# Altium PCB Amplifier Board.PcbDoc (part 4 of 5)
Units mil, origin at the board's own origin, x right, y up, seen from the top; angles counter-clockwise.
Board outline 6000 x 4000 mil, 6 copper layers (Top Layer, GND, VCC, InternalPlane3, InternalPlane4, Bottom Layer); 880 components, 519 nets, 2020 pads, 372 vias.
Unrouted connection lines stored in the file: 585.
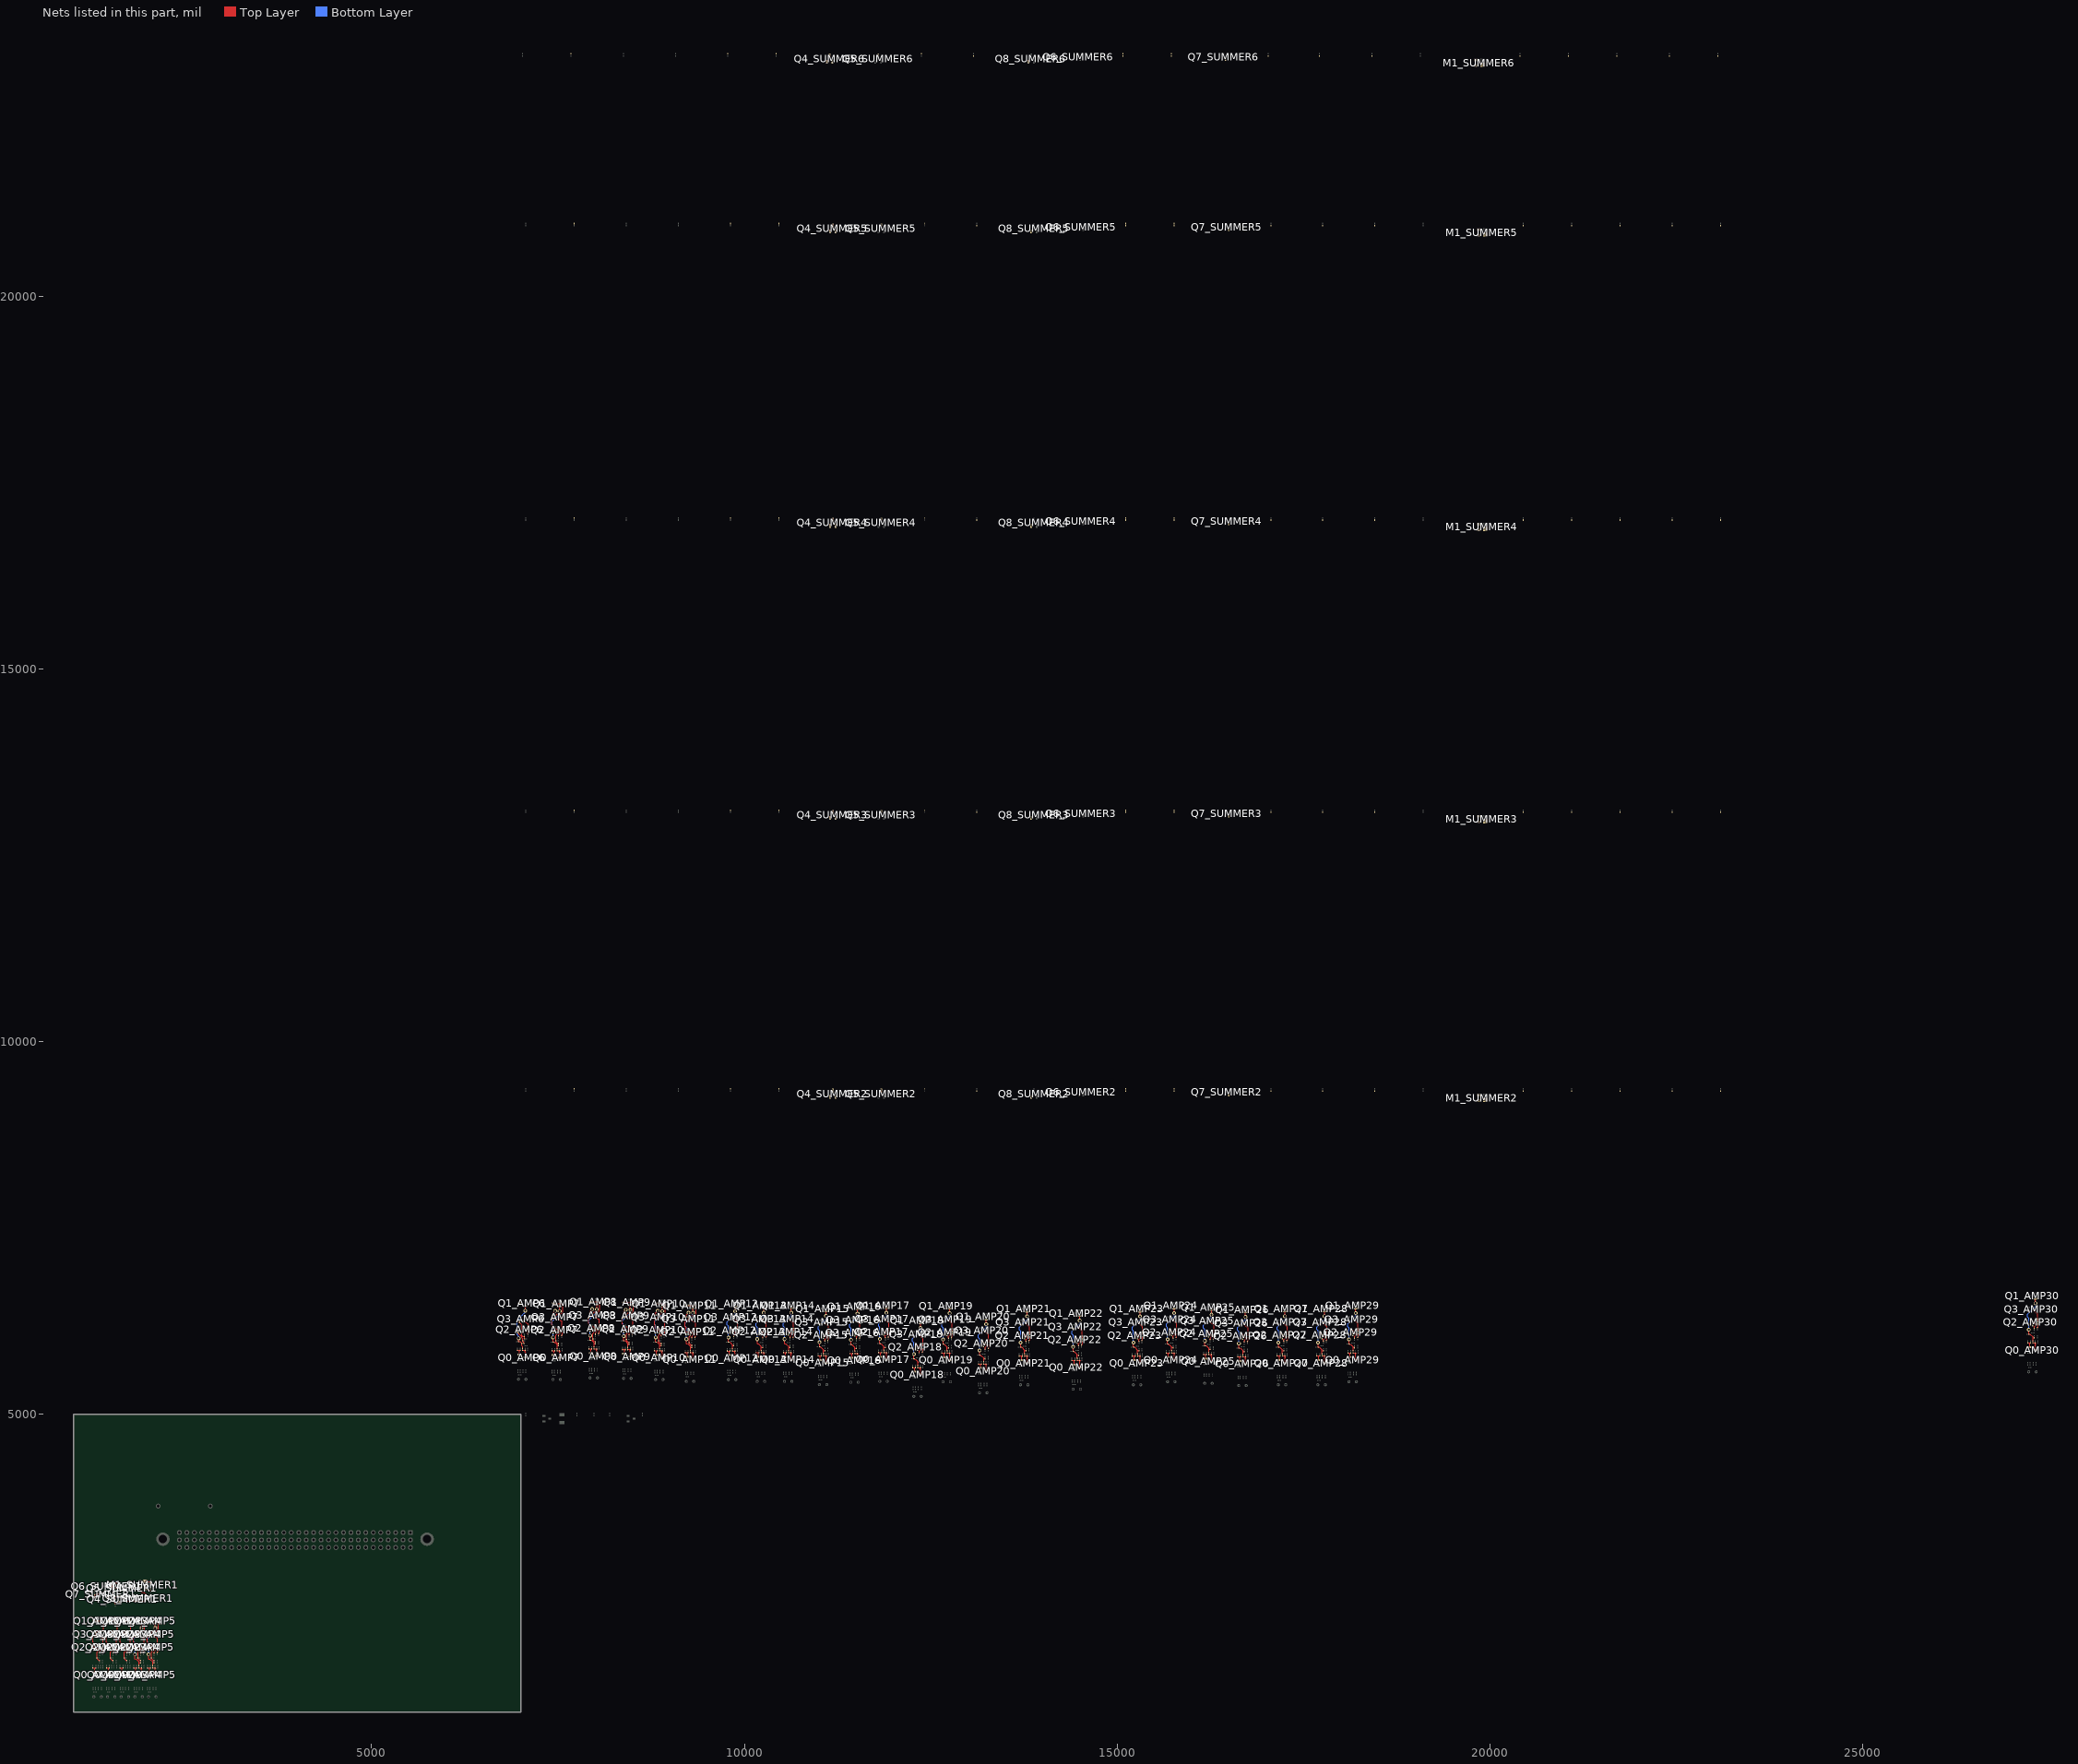
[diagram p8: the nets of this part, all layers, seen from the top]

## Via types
v1: diameter 50, hole 28, Top Layer to Bottom Layer, 371 vias
v2: diameter 50, hole 28, Top Layer to Bottom Layer, tented top, 1 vias

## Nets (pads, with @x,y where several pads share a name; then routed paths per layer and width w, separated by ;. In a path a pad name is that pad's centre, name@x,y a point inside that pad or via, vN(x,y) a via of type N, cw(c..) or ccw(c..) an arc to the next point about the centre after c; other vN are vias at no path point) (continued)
NetC4_AMP4_1: C4_AMP4.1 Q0_AMP4.3 R6_AMP4.1 | length 137.1
  Top Layer w7: C4_AMP4.1@1880,1596.22 R6_AMP4.1@1913,1596.22 ; Q0_AMP4.3@1915.34,1501.56 1915.34,1568.66 1913,1571 R6_AMP4.1@1913,1596.22 ; 1919,1590.22 R6_AMP4.1@1913,1596.22
NetC4_AMP4_2: C4_AMP4.2 Q1_AMP4.1 R2_AMP4.1 R3_AMP4.2 | length 660.4
  Top Layer w7: R3_AMP4.2@1826,1715.78 v1(1826,1776) ; R3_AMP4.2@1827.78,1714 1839,1714 ; 1842,1714 1880,1676 C4_AMP4.2@1880,1623.78 ; 1880,1666 R2_AMP4.1@1898.22,1666 ; v1@1915.34,2130.34 Q1_AMP4.1@1915.34,2191.6
  Bottom Layer w7: v1(1826,1776) 1826,1931 1809,1948 1809,1984 1914,2089 v1(1914,2129)
NetC4_AMP5_1: C4_AMP5.1 Q0_AMP5.3 R6_AMP5.1 | length 137.1
  Top Layer w7: C4_AMP5.1@2063,1596.22 R6_AMP5.1@2096,1596.22 ; Q0_AMP5.3@2098.34,1501.56 2098.34,1568.66 2096,1571 R6_AMP5.1@2096,1596.22 ; 2102,1590.22 R6_AMP5.1@2096,1596.22
NetC4_AMP5_2: C4_AMP5.2 Q1_AMP5.1 R2_AMP5.1 R3_AMP5.2 | length 660.4
  Top Layer w7: R3_AMP5.2@2009,1715.78 v1(2009,1776) ; R3_AMP5.2@2010.78,1714 2022,1714 ; 2025,1714 2063,1676 C4_AMP5.2@2063,1623.78 ; 2063,1666 R2_AMP5.1@2081.22,1666 ; v1@2098.34,2130.34 Q1_AMP5.1@2098.34,2191.6
  Bottom Layer w7: v1(2009,1776) 2009,1931 1992,1948 1992,1984 2097,2089 v1(2097,2129)
NetC4_AMP6_1: C4_AMP6.1 Q0_AMP6.3 R6_AMP6.1 | length 137.1
  Top Layer w7: C4_AMP6.1@7026,5856.22 R6_AMP6.1@7059,5856.22 ; Q0_AMP6.3@7061.34,5761.56 7061.34,5828.66 7059,5831 R6_AMP6.1@7059,5856.22 ; 7065,5850.22 R6_AMP6.1@7059,5856.22
NetC4_AMP6_2: C4_AMP6.2 Q1_AMP6.1 R2_AMP6.1 R3_AMP6.2 | length 653.2
  Top Layer w7: R3_AMP6.2@6972.4,5974 v1@6972.4,6018.6 ; R3_AMP6.2@6973.78,5974 6992.22,5974 R2_AMP6.1@7016.22,5950 7016.22,5922.78 7026,5913 C4_AMP6.2@7026,5883.78 ; v1@7061.34,6390.34 Q1_AMP6.1@7061.34,6451.6
  Bottom Layer w7: v1(6972,6019) 6972,6046 6950,6068 6950,6256 7060,6366 v1(7060,6389)
NetC4_AMP7_1: C4_AMP7.1 Q0_AMP7.3 R6_AMP7.1 | length 137.1
  Top Layer w7: C4_AMP7.1@7488,5851.22 R6_AMP7.1@7521,5851.22 ; Q0_AMP7.3@7523.34,5756.56 7523.34,5823.66 7521,5826 R6_AMP7.1@7521,5851.22 ; 7527,5845.22 R6_AMP7.1@7521,5851.22
NetC4_AMP7_2: C4_AMP7.2 Q1_AMP7.1 R2_AMP7.1 R3_AMP7.2 | length 660.4
  Top Layer w7: R3_AMP7.2@7434,5970.78 v1(7434,6031) ; R3_AMP7.2@7435.78,5969 7447,5969 ; 7450,5969 7488,5931 C4_AMP7.2@7488,5878.78 ; 7488,5921 R2_AMP7.1@7506.22,5921 ; v1@7523.34,6385.34 Q1_AMP7.1@7523.34,6446.6
  Bottom Layer w7: v1(7434,6031) 7434,6186 7417,6203 7417,6239 7522,6344 v1(7522,6384)
NetC4_AMP8_1: C4_AMP8.1 Q0_AMP8.3 R6_AMP8.1 | length 137.1
  Top Layer w7: C4_AMP8.1@7985,5875.22 R6_AMP8.1@8018,5875.22 ; Q0_AMP8.3@8020.34,5780.56 8020.34,5847.66 8018,5850 R6_AMP8.1@8018,5875.22 ; 8024,5869.22 R6_AMP8.1@8018,5875.22
NetC4_AMP8_2: C4_AMP8.2 Q1_AMP8.1 R2_AMP8.1 R3_AMP8.2 | length 660.4
  Top Layer w7: R3_AMP8.2@7931,5994.78 v1(7931,6055) ; R3_AMP8.2@7932.78,5993 7944,5993 ; 7947,5993 7985,5955 C4_AMP8.2@7985,5902.78 ; 7985,5945 R2_AMP8.1@8003.22,5945 ; v1@8020.34,6409.34 Q1_AMP8.1@8020.34,6470.6
  Bottom Layer w7: v1(7931,6055) 7931,6210 7914,6227 7914,6263 8019,6368 v1(8019,6408)
NetC4_AMP9_1: C4_AMP9.1 Q0_AMP9.3 R6_AMP9.1 | length 137.1
  Top Layer w7: C4_AMP9.1@8436,5868.22 R6_AMP9.1@8469,5868.22 ; Q0_AMP9.3@8471.34,5773.56 8471.34,5840.66 8469,5843 R6_AMP9.1@8469,5868.22 ; 8475,5862.22 R6_AMP9.1@8469,5868.22
NetC4_AMP9_2: C4_AMP9.2 Q1_AMP9.1 R2_AMP9.1 R3_AMP9.2 | length 660.4
  Top Layer w7: R3_AMP9.2@8382,5987.78 v1(8382,6048) ; R3_AMP9.2@8383.78,5986 8395,5986 ; 8398,5986 8436,5948 C4_AMP9.2@8436,5895.78 ; 8436,5938 R2_AMP9.1@8454.22,5938 ; v1@8471.34,6402.34 Q1_AMP9.1@8471.34,6463.6
  Bottom Layer w7: v1(8382,6048) 8382,6203 8365,6220 8365,6256 8470,6361 v1(8470,6401)
NetC4_AMP10_1: C4_AMP10.1 Q0_AMP10.3 R6_AMP10.1 | length 137.1
  Top Layer w7: C4_AMP10.1@8865,5851.22 R6_AMP10.1@8898,5851.22 ; Q0_AMP10.3@8900.34,5756.56 8900.34,5823.66 8898,5826 R6_AMP10.1@8898,5851.22 ; 8904,5845.22 R6_AMP10.1@8898,5851.22
NetC4_AMP10_2: C4_AMP10.2 Q1_AMP10.1 R2_AMP10.1 R3_AMP10.2 | length 660.4
  Top Layer w7: R3_AMP10.2@8811,5970.78 v1(8811,6031) ; R3_AMP10.2@8812.78,5969 8824,5969 ; 8827,5969 8865,5931 C4_AMP10.2@8865,5878.78 ; 8865,5921 R2_AMP10.1@8883.22,5921 ; v1@8900.34,6385.34 Q1_AMP10.1@8900.34,6446.6
  Bottom Layer w7: v1(8811,6031) 8811,6186 8794,6203 8794,6239 8899,6344 v1(8899,6384)
NetC4_AMP11_1: C4_AMP11.1 Q0_AMP11.3 R6_AMP11.1 | length 137.1
  Top Layer w7: C4_AMP11.1@9277,5827.22 R6_AMP11.1@9310,5827.22 ; Q0_AMP11.3@9312.34,5732.56 9312.34,5799.66 9310,5802 R6_AMP11.1@9310,5827.22 ; 9316,5821.22 R6_AMP11.1@9310,5827.22
NetC4_AMP11_2: C4_AMP11.2 Q1_AMP11.1 R2_AMP11.1 R3_AMP11.2 | length 660.4
  Top Layer w7: R3_AMP11.2@9223,5946.78 v1(9223,6007) ; R3_AMP11.2@9224.78,5945 9236,5945 ; 9239,5945 9277,5907 C4_AMP11.2@9277,5854.78 ; 9277,5897 R2_AMP11.1@9295.22,5897 ; v1@9312.34,6361.34 Q1_AMP11.1@9312.34,6422.6
  Bottom Layer w7: v1(9223,6007) 9223,6162 9206,6179 9206,6215 9311,6320 v1(9311,6360)
NetC4_AMP12_1: C4_AMP12.1 Q0_AMP12.3 R6_AMP12.1 | length 137.1
  Top Layer w7: C4_AMP12.1@9841,5849.22 R6_AMP12.1@9874,5849.22 ; Q0_AMP12.3@9876.34,5754.56 9876.34,5821.66 9874,5824 R6_AMP12.1@9874,5849.22 ; 9880,5843.22 R6_AMP12.1@9874,5849.22
NetC4_AMP12_2: C4_AMP12.2 Q1_AMP12.1 R2_AMP12.1 R3_AMP12.2 | length 660.4
  Top Layer w7: R3_AMP12.2@9787,5968.78 v1(9787,6029) ; R3_AMP12.2@9788.78,5967 9800,5967 ; 9803,5967 9841,5929 C4_AMP12.2@9841,5876.78 ; 9841,5919 R2_AMP12.1@9859.22,5919 ; v1@9876.34,6383.34 Q1_AMP12.1@9876.34,6444.6
  Bottom Layer w7: v1(9787,6029) 9787,6184 9770,6201 9770,6237 9875,6342 v1(9875,6382)
NetC4_AMP13_1: C4_AMP13.1 Q0_AMP13.3 R6_AMP13.1 | length 137.1
  Top Layer w7: C4_AMP13.1@10228,5827.22 R6_AMP13.1@10261,5827.22 ; Q0_AMP13.3@10263.34,5732.56 10263.34,5799.66 10261,5802 R6_AMP13.1@10261,5827.22 ; 10267,5821.22 R6_AMP13.1@10261,5827.22
NetC4_AMP13_2: C4_AMP13.2 Q1_AMP13.1 R2_AMP13.1 R3_AMP13.2 | length 660.4
  Top Layer w7: R3_AMP13.2@10174,5946.78 v1(10174,6007) ; R3_AMP13.2@10175.78,5945 10187,5945 ; 10190,5945 10228,5907 C4_AMP13.2@10228,5854.78 ; 10228,5897 R2_AMP13.1@10246.22,5897 ; v1@10263.34,6361.34 Q1_AMP13.1@10263.34,6422.6
  Bottom Layer w7: v1(10174,6007) 10174,6162 10157,6179 10157,6215 10262,6320 v1(10262,6360)
NetC4_AMP14_1: C4_AMP14.1 Q0_AMP14.3 R6_AMP14.1 | length 137.1
  Top Layer w7: C4_AMP14.1@10594,5827.22 R6_AMP14.1@10627,5827.22 ; Q0_AMP14.3@10629.34,5732.56 10629.34,5799.66 10627,5802 R6_AMP14.1@10627,5827.22 ; 10633,5821.22 R6_AMP14.1@10627,5827.22
NetC4_AMP14_2: C4_AMP14.2 Q1_AMP14.1 R2_AMP14.1 R3_AMP14.2 | length 660.4
  Top Layer w7: R3_AMP14.2@10540,5946.78 v1(10540,6007) ; R3_AMP14.2@10541.78,5945 10553,5945 ; 10556,5945 10594,5907 C4_AMP14.2@10594,5854.78 ; 10594,5897 R2_AMP14.1@10612.22,5897 ; v1@10629.34,6361.34 Q1_AMP14.1@10629.34,6422.6
  Bottom Layer w7: v1(10540,6007) 10540,6162 10523,6179 10523,6215 10628,6320 v1(10628,6360)
NetC4_AMP15_1: C4_AMP15.1 Q0_AMP15.3 R6_AMP15.1 | length 137.1
  Top Layer w7: C4_AMP15.1@11062,5784.22 R6_AMP15.1@11095,5784.22 ; Q0_AMP15.3@11097.34,5689.56 11097.34,5756.66 11095,5759 R6_AMP15.1@11095,5784.22 ; 11101,5778.22 R6_AMP15.1@11095,5784.22
NetC4_AMP15_2: C4_AMP15.2 Q1_AMP15.1 R2_AMP15.1 R3_AMP15.2 | length 660.4
  Top Layer w7: R3_AMP15.2@11008,5903.78 v1(11008,5964) ; R3_AMP15.2@11009.78,5902 11021,5902 ; 11024,5902 11062,5864 C4_AMP15.2@11062,5811.78 ; 11062,5854 R2_AMP15.1@11080.22,5854 ; v1@11097.34,6318.34 Q1_AMP15.1@11097.34,6379.6
  Bottom Layer w7: v1(11008,5964) 11008,6119 10991,6136 10991,6172 11096,6277 v1(11096,6317)
NetC4_AMP16_1: C4_AMP16.1 Q0_AMP16.3 R6_AMP16.1 | length 137.1
  Top Layer w7: C4_AMP16.1@11484,5816.22 R6_AMP16.1@11517,5816.22 ; Q0_AMP16.3@11519.34,5721.56 11519.34,5788.66 11517,5791 R6_AMP16.1@11517,5816.22 ; 11523,5810.22 R6_AMP16.1@11517,5816.22
NetC4_AMP16_2: C4_AMP16.2 Q1_AMP16.1 R2_AMP16.1 R3_AMP16.2 | length 660.4
  Top Layer w7: R3_AMP16.2@11430,5935.78 v1(11430,5996) ; R3_AMP16.2@11431.78,5934 11443,5934 ; 11446,5934 11484,5896 C4_AMP16.2@11484,5843.78 ; 11484,5886 R2_AMP16.1@11502.22,5886 ; v1@11519.34,6350.34 Q1_AMP16.1@11519.34,6411.6
  Bottom Layer w7: v1(11430,5996) 11430,6151 11413,6168 11413,6204 11518,6309 v1(11518,6349)
NetC4_AMP17_1: C4_AMP17.1 Q0_AMP17.3 R6_AMP17.1 | length 137.1
  Top Layer w7: C4_AMP17.1@11872,5828.22 R6_AMP17.1@11905,5828.22 ; Q0_AMP17.3@11907.34,5733.56 11907.34,5800.66 11905,5803 R6_AMP17.1@11905,5828.22 ; 11911,5822.22 R6_AMP17.1@11905,5828.22
NetC4_AMP17_2: C4_AMP17.2 Q1_AMP17.1 R2_AMP17.1 R3_AMP17.2 | length 660.4
  Top Layer w7: R3_AMP17.2@11818,5947.78 v1(11818,6008) ; R3_AMP17.2@11819.78,5946 11831,5946 ; 11834,5946 11872,5908 C4_AMP17.2@11872,5855.78 ; 11872,5898 R2_AMP17.1@11890.22,5898 ; v1@11907.34,6362.34 Q1_AMP17.1@11907.34,6423.6
  Bottom Layer w7: v1(11818,6008) 11818,6163 11801,6180 11801,6216 11906,6321 v1(11906,6361)
NetC4_AMP18_1: C4_AMP18.1 Q0_AMP18.3 R6_AMP18.1 | length 137.1
  Top Layer w7: C4_AMP18.1@12328,5626.22 R6_AMP18.1@12361,5626.22 ; Q0_AMP18.3@12363.34,5531.56 12363.34,5598.66 12361,5601 R6_AMP18.1@12361,5626.22 ; 12367,5620.22 R6_AMP18.1@12361,5626.22
NetC4_AMP18_2: C4_AMP18.2 Q1_AMP18.1 R2_AMP18.1 R3_AMP18.2 | length 660.4
  Top Layer w7: R3_AMP18.2@12274,5745.78 v1(12274,5806) ; R3_AMP18.2@12275.78,5744 12287,5744 ; 12290,5744 12328,5706 C4_AMP18.2@12328,5653.78 ; 12328,5696 R2_AMP18.1@12346.22,5696 ; v1@12363.34,6160.34 Q1_AMP18.1@12363.34,6221.6
  Bottom Layer w7: v1(12274,5806) 12274,5961 12257,5978 12257,6014 12362,6119 v1(12362,6159)
NetC4_AMP19_1: C4_AMP19.1 Q0_AMP19.3 R6_AMP19.1 | length 137.1
  Top Layer w7: C4_AMP19.1@12720,5822.22 R6_AMP19.1@12753,5822.22 ; Q0_AMP19.3@12755.34,5727.56 12755.34,5794.66 12753,5797 R6_AMP19.1@12753,5822.22 ; 12759,5816.22 R6_AMP19.1@12753,5822.22
NetC4_AMP19_2: C4_AMP19.2 Q1_AMP19.1 R2_AMP19.1 R3_AMP19.2 | length 660.4
  Top Layer w7: R3_AMP19.2@12666,5941.78 v1(12666,6002) ; R3_AMP19.2@12667.78,5940 12679,5940 ; 12682,5940 12720,5902 C4_AMP19.2@12720,5849.78 ; 12720,5892 R2_AMP19.1@12738.22,5892 ; v1@12755.34,6356.34 Q1_AMP19.1@12755.34,6417.6
  Bottom Layer w7: v1(12666,6002) 12666,6157 12649,6174 12649,6210 12754,6315 v1(12754,6355)
NetC4_AMP20_1: C4_AMP20.1 Q0_AMP20.3 R6_AMP20.1 | length 137.1
  Top Layer w7: C4_AMP20.1@13210,5675.22 R6_AMP20.1@13243,5675.22 ; Q0_AMP20.3@13245.34,5580.56 13245.34,5647.66 13243,5650 R6_AMP20.1@13243,5675.22 ; 13249,5669.22 R6_AMP20.1@13243,5675.22
NetC4_AMP20_2: C4_AMP20.2 Q1_AMP20.1 R2_AMP20.1 R3_AMP20.2 | length 660.4
  Top Layer w7: R3_AMP20.2@13156,5794.78 v1(13156,5855) ; R3_AMP20.2@13157.78,5793 13169,5793 ; 13172,5793 13210,5755 C4_AMP20.2@13210,5702.78 ; 13210,5745 R2_AMP20.1@13228.22,5745 ; v1@13245.34,6209.34 Q1_AMP20.1@13245.34,6270.6
  Bottom Layer w7: v1(13156,5855) 13156,6010 13139,6027 13139,6063 13244,6168 v1(13244,6208)
NetC4_AMP21_1: C4_AMP21.1 Q0_AMP21.3 R6_AMP21.1 | length 137.1
  Top Layer w7: C4_AMP21.1@13760,5781.22 R6_AMP21.1@13793,5781.22 ; Q0_AMP21.3@13795.34,5686.56 13795.34,5753.66 13793,5756 R6_AMP21.1@13793,5781.22 ; 13799,5775.22 R6_AMP21.1@13793,5781.22
NetC4_AMP21_2: C4_AMP21.2 Q1_AMP21.1 R2_AMP21.1 R3_AMP21.2 | length 660.4
  Top Layer w7: R3_AMP21.2@13706,5900.78 v1(13706,5961) ; R3_AMP21.2@13707.78,5899 13719,5899 ; 13722,5899 13760,5861 C4_AMP21.2@13760,5808.78 ; 13760,5851 R2_AMP21.1@13778.22,5851 ; v1@13795.34,6315.34 Q1_AMP21.1@13795.34,6376.6
  Bottom Layer w7: v1(13706,5961) 13706,6116 13689,6133 13689,6169 13794,6274 v1(13794,6314)
NetC4_AMP22_1: C4_AMP22.1 Q0_AMP22.3 R6_AMP22.1 | length 137.1
  Top Layer w7: C4_AMP22.1@14465,5723.22 R6_AMP22.1@14498,5723.22 ; Q0_AMP22.3@14500.34,5628.56 14500.34,5695.66 14498,5698 R6_AMP22.1@14498,5723.22 ; 14504,5717.22 R6_AMP22.1@14498,5723.22
NetC4_AMP22_2: C4_AMP22.2 Q1_AMP22.1 R2_AMP22.1 R3_AMP22.2 | length 660.4
  Top Layer w7: R3_AMP22.2@14411,5842.78 v1(14411,5903) ; R3_AMP22.2@14412.78,5841 14424,5841 ; 14427,5841 14465,5803 C4_AMP22.2@14465,5750.78 ; 14465,5793 R2_AMP22.1@14483.22,5793 ; v1@14500.34,6257.34 Q1_AMP22.1@14500.34,6318.6
  Bottom Layer w7: v1(14411,5903) 14411,6058 14394,6075 14394,6111 14499,6216 v1(14499,6256)
NetC4_AMP23_1: C4_AMP23.1 Q0_AMP23.3 R6_AMP23.1 | length 137.1
  Top Layer w7: C4_AMP23.1@15274,5781.22 R6_AMP23.1@15307,5781.22 ; Q0_AMP23.3@15309.34,5686.56 15309.34,5753.66 15307,5756 R6_AMP23.1@15307,5781.22 ; 15313,5775.22 R6_AMP23.1@15307,5781.22
NetC4_AMP23_2: C4_AMP23.2 Q1_AMP23.1 R2_AMP23.1 R3_AMP23.2 | length 660.4
  Top Layer w7: R3_AMP23.2@15220,5900.78 v1(15220,5961) ; R3_AMP23.2@15221.78,5899 15233,5899 ; 15236,5899 15274,5861 C4_AMP23.2@15274,5808.78 ; 15274,5851 R2_AMP23.1@15292.22,5851 ; v1@15309.34,6315.34 Q1_AMP23.1@15309.34,6376.6
  Bottom Layer w7: v1(15220,5961) 15220,6116 15203,6133 15203,6169 15308,6274 v1(15308,6314)
NetC4_AMP24_1: C4_AMP24.1 Q0_AMP24.3 R6_AMP24.1 | length 137.1
  Top Layer w7: C4_AMP24.1@15732,5823.22 R6_AMP24.1@15765,5823.22 ; Q0_AMP24.3@15767.34,5728.56 15767.34,5795.66 15765,5798 R6_AMP24.1@15765,5823.22 ; 15771,5817.22 R6_AMP24.1@15765,5823.22
NetC4_AMP24_2: C4_AMP24.2 Q1_AMP24.1 R2_AMP24.1 R3_AMP24.2 | length 660.4
  Top Layer w7: R3_AMP24.2@15678,5942.78 v1(15678,6003) ; R3_AMP24.2@15679.78,5941 15691,5941 ; 15694,5941 15732,5903 C4_AMP24.2@15732,5850.78 ; 15732,5893 R2_AMP24.1@15750.22,5893 ; v1@15767.34,6357.34 Q1_AMP24.1@15767.34,6418.6
  Bottom Layer w7: v1(15678,6003) 15678,6158 15661,6175 15661,6211 15766,6316 v1(15766,6356)
NetC4_AMP25_1: C4_AMP25.1 Q0_AMP25.3 R6_AMP25.1 | length 137.1
  Top Layer w7: C4_AMP25.1@16231,5802.22 R6_AMP25.1@16264,5802.22 ; Q0_AMP25.3@16266.34,5707.56 16266.34,5774.66 16264,5777 R6_AMP25.1@16264,5802.22 ; 16270,5796.22 R6_AMP25.1@16264,5802.22
NetC4_AMP25_2: C4_AMP25.2 Q1_AMP25.1 R2_AMP25.1 R3_AMP25.2 | length 660.4
  Top Layer w7: R3_AMP25.2@16177,5921.78 v1(16177,5982) ; R3_AMP25.2@16178.78,5920 16190,5920 ; 16193,5920 16231,5882 C4_AMP25.2@16231,5829.78 ; 16231,5872 R2_AMP25.1@16249.22,5872 ; v1@16266.34,6336.34 Q1_AMP25.1@16266.34,6397.6
  Bottom Layer w7: v1(16177,5982) 16177,6137 16160,6154 16160,6190 16265,6295 v1(16265,6335)
NetC4_AMP26_1: C4_AMP26.1 Q0_AMP26.3 R6_AMP26.1 | length 137.1
  Top Layer w7: C4_AMP26.1@16688,5771.22 R6_AMP26.1@16721,5771.22 ; Q0_AMP26.3@16723.34,5676.56 16723.34,5743.66 16721,5746 R6_AMP26.1@16721,5771.22 ; 16727,5765.22 R6_AMP26.1@16721,5771.22
NetC4_AMP26_2: C4_AMP26.2 Q1_AMP26.1 R2_AMP26.1 R3_AMP26.2 | length 660.4
  Top Layer w7: R3_AMP26.2@16634,5890.78 v1(16634,5951) ; R3_AMP26.2@16635.78,5889 16647,5889 ; 16650,5889 16688,5851 C4_AMP26.2@16688,5798.78 ; 16688,5841 R2_AMP26.1@16706.22,5841 ; v1@16723.34,6305.34 Q1_AMP26.1@16723.34,6366.6
  Bottom Layer w7: v1(16634,5951) 16634,6106 16617,6123 16617,6159 16722,6264 v1(16722,6304)
NetC4_AMP27_1: C4_AMP27.1 Q0_AMP27.3 R6_AMP27.1 | length 137.1
  Top Layer w7: C4_AMP27.1@17218,5782.22 R6_AMP27.1@17251,5782.22 ; Q0_AMP27.3@17253.34,5687.56 17253.34,5754.66 17251,5757 R6_AMP27.1@17251,5782.22 ; 17257,5776.22 R6_AMP27.1@17251,5782.22
NetC4_AMP27_2: C4_AMP27.2 Q1_AMP27.1 R2_AMP27.1 R3_AMP27.2 | length 660.4
  Top Layer w7: R3_AMP27.2@17164,5901.78 v1(17164,5962) ; R3_AMP27.2@17165.78,5900 17177,5900 ; 17180,5900 17218,5862 C4_AMP27.2@17218,5809.78 ; 17218,5852 R2_AMP27.1@17236.22,5852 ; v1@17253.34,6316.34 Q1_AMP27.1@17253.34,6377.6
  Bottom Layer w7: v1(17164,5962) 17164,6117 17147,6134 17147,6170 17252,6275 v1(17252,6315)
NetC4_AMP28_1: C4_AMP28.1 Q0_AMP28.3 R6_AMP28.1 | length 137.1
  Top Layer w7: C4_AMP28.1@17749,5782.22 R6_AMP28.1@17782,5782.22 ; Q0_AMP28.3@17784.34,5687.56 17784.34,5754.66 17782,5757 R6_AMP28.1@17782,5782.22 ; 17788,5776.22 R6_AMP28.1@17782,5782.22
NetC4_AMP28_2: C4_AMP28.2 Q1_AMP28.1 R2_AMP28.1 R3_AMP28.2 | length 660.4
  Top Layer w7: R3_AMP28.2@17695,5901.78 v1(17695,5962) ; R3_AMP28.2@17696.78,5900 17708,5900 ; 17711,5900 17749,5862 C4_AMP28.2@17749,5809.78 ; 17749,5852 R2_AMP28.1@17767.22,5852 ; v1@17784.34,6316.34 Q1_AMP28.1@17784.34,6377.6
  Bottom Layer w7: v1(17695,5962) 17695,6117 17678,6134 17678,6170 17783,6275 v1(17783,6315)
NetC4_AMP29_1: C4_AMP29.1 Q0_AMP29.3 R6_AMP29.1 | length 137.1
  Top Layer w7: C4_AMP29.1@18166,5823.22 R6_AMP29.1@18199,5823.22 ; Q0_AMP29.3@18201.34,5728.56 18201.34,5795.66 18199,5798 R6_AMP29.1@18199,5823.22 ; 18205,5817.22 R6_AMP29.1@18199,5823.22
NetC4_AMP29_2: C4_AMP29.2 Q1_AMP29.1 R2_AMP29.1 R3_AMP29.2 | length 660.4
  Top Layer w7: R3_AMP29.2@18112,5942.78 v1(18112,6003) ; R3_AMP29.2@18113.78,5941 18125,5941 ; 18128,5941 18166,5903 C4_AMP29.2@18166,5850.78 ; 18166,5893 R2_AMP29.1@18184.22,5893 ; v1@18201.34,6357.34 Q1_AMP29.1@18201.34,6418.6
  Bottom Layer w7: v1(18112,6003) 18112,6158 18095,6175 18095,6211 18200,6316 v1(18200,6356)
NetC4_AMP30_1: C4_AMP30.1 Q0_AMP30.3 R6_AMP30.1 | length 137.1
  Top Layer w7: C4_AMP30.1@27284,5955.22 R6_AMP30.1@27317,5955.22 ; Q0_AMP30.3@27319.34,5860.56 27319.34,5927.66 27317,5930 R6_AMP30.1@27317,5955.22 ; 27323,5949.22 R6_AMP30.1@27317,5955.22
NetC4_AMP30_2: C4_AMP30.2 Q1_AMP30.1 R2_AMP30.1 R3_AMP30.2 | length 660.4
  Top Layer w7: R3_AMP30.2@27230,6074.78 v1(27230,6135) ; R3_AMP30.2@27231.78,6073 27243,6073 ; 27246,6073 27284,6035 C4_AMP30.2@27284,5982.78 ; 27284,6025 R2_AMP30.1@27302.22,6025 ; v1@27319.34,6489.34 Q1_AMP30.1@27319.34,6550.6
  Bottom Layer w7: v1(27230,6135) 27230,6290 27213,6307 27213,6343 27318,6448 v1(27318,6488)
NetC5_AMP1_1: C5_AMP1.1 Q2_AMP1.2 R5_AMP1.1 | length 157.6
  Top Layer w7: 1304.57,1909.43 1358,1856 1368.22,1856 C5_AMP1.1@1369,1855.22 1369,1835.22 1349,1815.22 R5_AMP1.1@1349,1792.78
NetC5_AMP2_1: C5_AMP2.1 Q2_AMP2.2 R5_AMP2.1 | length 157.6
  Top Layer w7: 1487.57,1909.43 1541,1856 1551.22,1856 C5_AMP2.1@1552,1855.22 1552,1835.22 1532,1815.22 R5_AMP2.1@1532,1792.78
NetC5_AMP3_1: C5_AMP3.1 Q2_AMP3.2 R5_AMP3.1 | length 157.6
  Top Layer w7: 1670.57,1909.43 1724,1856 1734.22,1856 C5_AMP3.1@1735,1855.22 1735,1835.22 1715,1815.22 R5_AMP3.1@1715,1792.78
NetC5_AMP4_1: C5_AMP4.1 Q2_AMP4.2 R5_AMP4.1 | length 157.6
  Top Layer w7: 1854.57,1909.43 1908,1856 1918.22,1856 C5_AMP4.1@1919,1855.22 1919,1835.22 1899,1815.22 R5_AMP4.1@1899,1792.78
NetC5_AMP5_1: C5_AMP5.1 Q2_AMP5.2 R5_AMP5.1 | length 157.6
  Top Layer w7: 2037.57,1909.43 2091,1856 2101.22,1856 C5_AMP5.1@2102,1855.22 2102,1835.22 2082,1815.22 R5_AMP5.1@2082,1792.78
NetC5_AMP6_1: C5_AMP6.1 Q2_AMP6.2 R5_AMP6.1 | length 116
  Top Layer w7: Q2_AMP6.2@7013.59,6099.57 7013.59,6059.45 7029.6,6043.44 C5_AMP6.1@7054.22,6043.44 ; R5_AMP6.1@7050,6015.6 C5_AMP6.1@7050,6044.22
NetC5_AMP7_1: C5_AMP7.1 Q2_AMP7.2 R5_AMP7.1 | length 157.6
  Top Layer w7: 7462.57,6164.43 7516,6111 7526.22,6111 C5_AMP7.1@7527,6110.22 7527,6090.22 7507,6070.22 R5_AMP7.1@7507,6047.78
NetC5_AMP8_1: C5_AMP8.1 Q2_AMP8.2 R5_AMP8.1 | length 157.6
  Top Layer w7: 7959.57,6188.43 8013,6135 8023.22,6135 C5_AMP8.1@8024,6134.22 8024,6114.22 8004,6094.22 R5_AMP8.1@8004,6071.78
NetC5_AMP9_1: C5_AMP9.1 Q2_AMP9.2 R5_AMP9.1 | length 157.6
  Top Layer w7: 8410.57,6181.43 8464,6128 8474.22,6128 C5_AMP9.1@8475,6127.22 8475,6107.22 8455,6087.22 R5_AMP9.1@8455,6064.78
NetC5_AMP10_1: C5_AMP10.1 Q2_AMP10.2 R5_AMP10.1 | length 157.6
  Top Layer w7: 8839.57,6164.43 8893,6111 8903.22,6111 C5_AMP10.1@8904,6110.22 8904,6090.22 8884,6070.22 R5_AMP10.1@8884,6047.78
NetC5_AMP11_1: C5_AMP11.1 Q2_AMP11.2 R5_AMP11.1 | length 157.6
  Top Layer w7: 9251.57,6140.43 9305,6087 9315.22,6087 C5_AMP11.1@9316,6086.22 9316,6066.22 9296,6046.22 R5_AMP11.1@9296,6023.78
NetC5_AMP12_1: C5_AMP12.1 Q2_AMP12.2 R5_AMP12.1 | length 157.6
  Top Layer w7: 9815.57,6162.43 9869,6109 9879.22,6109 C5_AMP12.1@9880,6108.22 9880,6088.22 9860,6068.22 R5_AMP12.1@9860,6045.78
NetC5_AMP13_1: C5_AMP13.1 Q2_AMP13.2 R5_AMP13.1 | length 157.6
  Top Layer w7: 10202.57,6140.43 10256,6087 10266.22,6087 C5_AMP13.1@10267,6086.22 10267,6066.22 10247,6046.22 R5_AMP13.1@10247,6023.78
NetC5_AMP14_1: C5_AMP14.1 Q2_AMP14.2 R5_AMP14.1 | length 157.6
  Top Layer w7: 10568.57,6140.43 10622,6087 10632.22,6087 C5_AMP14.1@10633,6086.22 10633,6066.22 10613,6046.22 R5_AMP14.1@10613,6023.78
NetC5_AMP15_1: C5_AMP15.1 Q2_AMP15.2 R5_AMP15.1 | length 157.6
  Top Layer w7: 11036.57,6097.43 11090,6044 11100.22,6044 C5_AMP15.1@11101,6043.22 11101,6023.22 11081,6003.22 R5_AMP15.1@11081,5980.78
NetC5_AMP16_1: C5_AMP16.1 Q2_AMP16.2 R5_AMP16.1 | length 157.6
  Top Layer w7: 11458.57,6129.43 11512,6076 11522.22,6076 C5_AMP16.1@11523,6075.22 11523,6055.22 11503,6035.22 R5_AMP16.1@11503,6012.78
NetC5_AMP17_1: C5_AMP17.1 Q2_AMP17.2 R5_AMP17.1 | length 157.6
  Top Layer w7: 11846.57,6141.43 11900,6088 11910.22,6088 C5_AMP17.1@11911,6087.22 11911,6067.22 11891,6047.22 R5_AMP17.1@11891,6024.78
NetC5_AMP18_1: C5_AMP18.1 Q2_AMP18.2 R5_AMP18.1 | length 157.6
  Top Layer w7: 12302.57,5939.43 12356,5886 12366.22,5886 C5_AMP18.1@12367,5885.22 12367,5865.22 12347,5845.22 R5_AMP18.1@12347,5822.78
NetC5_AMP19_1: C5_AMP19.1 Q2_AMP19.2 R5_AMP19.1 | length 157.6
  Top Layer w7: 12694.57,6135.43 12748,6082 12758.22,6082 C5_AMP19.1@12759,6081.22 12759,6061.22 12739,6041.22 R5_AMP19.1@12739,6018.78
NetC5_AMP20_1: C5_AMP20.1 Q2_AMP20.2 R5_AMP20.1 | length 157.6
  Top Layer w7: 13184.57,5988.43 13238,5935 13248.22,5935 C5_AMP20.1@13249,5934.22 13249,5914.22 13229,5894.22 R5_AMP20.1@13229,5871.78
NetC5_AMP21_1: C5_AMP21.1 Q2_AMP21.2 R5_AMP21.1 | length 157.6
  Top Layer w7: 13734.57,6094.43 13788,6041 13798.22,6041 C5_AMP21.1@13799,6040.22 13799,6020.22 13779,6000.22 R5_AMP21.1@13779,5977.78
NetC5_AMP22_1: C5_AMP22.1 Q2_AMP22.2 R5_AMP22.1 | length 157.6
  Top Layer w7: 14439.57,6036.43 14493,5983 14503.22,5983 C5_AMP22.1@14504,5982.22 14504,5962.22 14484,5942.22 R5_AMP22.1@14484,5919.78
NetC5_AMP23_1: C5_AMP23.1 Q2_AMP23.2 R5_AMP23.1 | length 157.6
  Top Layer w7: 15248.57,6094.43 15302,6041 15312.22,6041 C5_AMP23.1@15313,6040.22 15313,6020.22 15293,6000.22 R5_AMP23.1@15293,5977.78
NetC5_AMP24_1: C5_AMP24.1 Q2_AMP24.2 R5_AMP24.1 | length 157.6
  Top Layer w7: 15706.57,6136.43 15760,6083 15770.22,6083 C5_AMP24.1@15771,6082.22 15771,6062.22 15751,6042.22 R5_AMP24.1@15751,6019.78
NetC5_AMP25_1: C5_AMP25.1 Q2_AMP25.2 R5_AMP25.1 | length 157.6
  Top Layer w7: 16205.57,6115.43 16259,6062 16269.22,6062 C5_AMP25.1@16270,6061.22 16270,6041.22 16250,6021.22 R5_AMP25.1@16250,5998.78
NetC5_AMP26_1: C5_AMP26.1 Q2_AMP26.2 R5_AMP26.1 | length 157.6
  Top Layer w7: 16662.57,6084.43 16716,6031 16726.22,6031 C5_AMP26.1@16727,6030.22 16727,6010.22 16707,5990.22 R5_AMP26.1@16707,5967.78
NetC5_AMP27_1: C5_AMP27.1 Q2_AMP27.2 R5_AMP27.1 | length 157.6
  Top Layer w7: 17192.57,6095.43 17246,6042 17256.22,6042 C5_AMP27.1@17257,6041.22 17257,6021.22 17237,6001.22 R5_AMP27.1@17237,5978.78
NetC5_AMP28_1: C5_AMP28.1 Q2_AMP28.2 R5_AMP28.1 | length 157.6
  Top Layer w7: 17723.57,6095.43 17777,6042 17787.22,6042 C5_AMP28.1@17788,6041.22 17788,6021.22 17768,6001.22 R5_AMP28.1@17768,5978.78
NetC5_AMP29_1: C5_AMP29.1 Q2_AMP29.2 R5_AMP29.1 | length 157.6
  Top Layer w7: 18140.57,6136.43 18194,6083 18204.22,6083 C5_AMP29.1@18205,6082.22 18205,6062.22 18185,6042.22 R5_AMP29.1@18185,6019.78
NetC5_AMP30_1: C5_AMP30.1 Q2_AMP30.2 R5_AMP30.1 | length 157.6
  Top Layer w7: 27258.57,6268.43 27312,6215 27322.22,6215 C5_AMP30.1@27323,6214.22 27323,6194.22 27303,6174.22 R5_AMP30.1@27303,6151.78
NetC5_SUMMER1_1: C5_SUMMER1.1 Q5_SUMMER1.3 R13_SUMMER1.1 | length 144.2
  Top Layer w7: C5_SUMMER1.1@1559,2664.6 Q5_SUMMER1.3@1610.26,2664.6 ; R13_SUMMER1.1@1559,2733.22 1576.78,2733.22 1595,2715 Q5_SUMMER1.3@1595,2665.6
NetC5_SUMMER1_2: C5_SUMMER1.2 Q6_SUMMER1.1 RC_SUMMER1.2 RD_SUMMER1.1 | length 139.8
  Top Layer w7: 1480.43,2715.59 1516.37,2715.59 RD_SUMMER1.1@1524,2723.22 ; RC_SUMMER1.2@1524,2665.78 RD_SUMMER1.1@1524,2724.6 ; 1524,2690 C5_SUMMER1.2@1558.22,2690
NetC5_SUMMER2_1: C5_SUMMER2.1 Q5_SUMMER2.3 R13_SUMMER2.1
NetC5_SUMMER2_2: C5_SUMMER2.2 Q6_SUMMER2.1 RC_SUMMER2.2 RD_SUMMER2.1
NetC5_SUMMER3_1: C5_SUMMER3.1 Q5_SUMMER3.3 R13_SUMMER3.1
NetC5_SUMMER3_2: C5_SUMMER3.2 Q6_SUMMER3.1 RC_SUMMER3.2 RD_SUMMER3.1
NetC5_SUMMER4_1: C5_SUMMER4.1 Q5_SUMMER4.3 R13_SUMMER4.1
NetC5_SUMMER4_2: C5_SUMMER4.2 Q6_SUMMER4.1 RC_SUMMER4.2 RD_SUMMER4.1
NetC5_SUMMER5_1: C5_SUMMER5.1 Q5_SUMMER5.3 R13_SUMMER5.1
NetC5_SUMMER5_2: C5_SUMMER5.2 Q6_SUMMER5.1 RC_SUMMER5.2 RD_SUMMER5.1
NetC5_SUMMER6_1: C5_SUMMER6.1 Q5_SUMMER6.3 R13_SUMMER6.1
NetC5_SUMMER6_2: C5_SUMMER6.2 Q6_SUMMER6.1 RC_SUMMER6.2 RD_SUMMER6.1
NetC6_AMP1_1: C6_AMP1.1 Q3_AMP1.2 R8_AMP1.1 | length 203.1
  Top Layer w7: 1346.43,2048 1346.43,2031.57 1375.93,2002.07 1394.4,2002.07 1396.78,1999.69 R8_AMP1.1@1396.78,1919 ; C6_AMP1.1@1399,1882.78 1399,1925.22
NetC6_AMP1_2: C6_AMP1.2 R7_AMP1.1 | length 56.6
  Top Layer w7: R7_AMP1.1@1389,1802.78 1399,1812.78 C6_AMP1.2@1399,1855.22
NetC6_AMP2_1: C6_AMP2.1 Q3_AMP2.2 R8_AMP2.1 | length 203.1
  Top Layer w7: 1529.43,2048 1529.43,2031.57 1558.93,2002.07 1577.4,2002.07 1579.78,1999.69 R8_AMP2.1@1579.78,1919 ; C6_AMP2.1@1582,1882.78 1582,1925.22
NetC6_AMP2_2: C6_AMP2.2 R7_AMP2.1 | length 56.6
  Top Layer w7: R7_AMP2.1@1572,1802.78 1582,1812.78 C6_AMP2.2@1582,1855.22
NetC6_AMP3_1: C6_AMP3.1 Q3_AMP3.2 R8_AMP3.1 | length 203.1
  Top Layer w7: 1712.43,2048 1712.43,2031.57 1741.93,2002.07 1760.4,2002.07 1762.78,1999.69 R8_AMP3.1@1762.78,1919 ; C6_AMP3.1@1765,1882.78 1765,1925.22
NetC6_AMP3_2: C6_AMP3.2 R7_AMP3.1 | length 56.6
  Top Layer w7: R7_AMP3.1@1755,1802.78 1765,1812.78 C6_AMP3.2@1765,1855.22
NetC6_AMP4_1: C6_AMP4.1 Q3_AMP4.2 R8_AMP4.1 | length 203.1
  Top Layer w7: 1896.43,2048 1896.43,2031.57 1925.93,2002.07 1944.4,2002.07 1946.78,1999.69 R8_AMP4.1@1946.78,1919 ; C6_AMP4.1@1949,1882.78 1949,1925.22
NetC6_AMP4_2: C6_AMP4.2 R7_AMP4.1 | length 56.6
  Top Layer w7: R7_AMP4.1@1939,1802.78 1949,1812.78 C6_AMP4.2@1949,1855.22
NetC6_AMP5_1: C6_AMP5.1 Q3_AMP5.2 R8_AMP5.1 | length 203.1
  Top Layer w7: 2079.43,2048 2079.43,2031.57 2108.93,2002.07 2127.4,2002.07 2129.78,1999.69 R8_AMP5.1@2129.78,1919 ; C6_AMP5.1@2132,1882.78 2132,1925.22
NetC6_AMP5_2: C6_AMP5.2 R7_AMP5.1 | length 56.6
  Top Layer w7: R7_AMP5.1@2122,1802.78 2132,1812.78 C6_AMP5.2@2132,1855.22
NetC6_AMP6_1: C6_AMP6.1 Q3_AMP6.2 R8_AMP6.1 | length 177.2
  Top Layer w7: Q3_AMP6.2@7035.59,6244.57 7057.68,6244.57 7100,6202.24 7100,6172.94 7095,6167.94 7095,6142.78 7084.59,6142.78 7075.59,6133.78 R8_AMP6.1@7065,6133.78
NetC6_AMP6_2: C6_AMP6.2 R7_AMP6.1 | length 42.4
  Top Layer w7: R7_AMP6.1@7095,6072.78 C6_AMP6.2@7095,6115.22
NetC6_AMP7_1: C6_AMP7.1 Q3_AMP7.2 R8_AMP7.1 | length 203.1
  Top Layer w7: 7504.43,6303 7504.43,6286.57 7533.93,6257.07 7552.4,6257.07 7554.78,6254.69 R8_AMP7.1@7554.78,6174 ; C6_AMP7.1@7557,6137.78 7557,6180.22
NetC6_AMP7_2: C6_AMP7.2 R7_AMP7.1 | length 56.6
  Top Layer w7: R7_AMP7.1@7547,6057.78 7557,6067.78 C6_AMP7.2@7557,6110.22
NetC6_AMP8_1: C6_AMP8.1 Q3_AMP8.2 R8_AMP8.1 | length 203.1
  Top Layer w7: 8001.43,6327 8001.43,6310.57 8030.93,6281.07 8049.4,6281.07 8051.78,6278.69 R8_AMP8.1@8051.78,6198 ; C6_AMP8.1@8054,6161.78 8054,6204.22
NetC6_AMP8_2: C6_AMP8.2 R7_AMP8.1 | length 56.6
  Top Layer w7: R7_AMP8.1@8044,6081.78 8054,6091.78 C6_AMP8.2@8054,6134.22
NetC6_AMP9_1: C6_AMP9.1 Q3_AMP9.2 R8_AMP9.1 | length 203.1
  Top Layer w7: 8452.43,6320 8452.43,6303.57 8481.93,6274.07 8500.4,6274.07 8502.78,6271.69 R8_AMP9.1@8502.78,6191 ; C6_AMP9.1@8505,6154.78 8505,6197.22
NetC6_AMP9_2: C6_AMP9.2 R7_AMP9.1 | length 56.6
  Top Layer w7: R7_AMP9.1@8495,6074.78 8505,6084.78 C6_AMP9.2@8505,6127.22
NetC6_AMP10_1: C6_AMP10.1 Q3_AMP10.2 R8_AMP10.1 | length 203.1
  Top Layer w7: 8881.43,6303 8881.43,6286.57 8910.93,6257.07 8929.4,6257.07 8931.78,6254.69 R8_AMP10.1@8931.78,6174 ; C6_AMP10.1@8934,6137.78 8934,6180.22
NetC6_AMP10_2: C6_AMP10.2 R7_AMP10.1 | length 56.6
  Top Layer w7: R7_AMP10.1@8924,6057.78 8934,6067.78 C6_AMP10.2@8934,6110.22
NetC6_AMP11_1: C6_AMP11.1 Q3_AMP11.2 R8_AMP11.1 | length 203.1
  Top Layer w7: 9293.43,6279 9293.43,6262.57 9322.93,6233.07 9341.4,6233.07 9343.78,6230.69 R8_AMP11.1@9343.78,6150 ; C6_AMP11.1@9346,6113.78 9346,6156.22
NetC6_AMP11_2: C6_AMP11.2 R7_AMP11.1 | length 56.6
  Top Layer w7: R7_AMP11.1@9336,6033.78 9346,6043.78 C6_AMP11.2@9346,6086.22
NetC6_AMP12_1: C6_AMP12.1 Q3_AMP12.2 R8_AMP12.1 | length 203.1
  Top Layer w7: 9857.43,6301 9857.43,6284.57 9886.93,6255.07 9905.4,6255.07 9907.78,6252.69 R8_AMP12.1@9907.78,6172 ; C6_AMP12.1@9910,6135.78 9910,6178.22
NetC6_AMP12_2: C6_AMP12.2 R7_AMP12.1 | length 56.6
  Top Layer w7: R7_AMP12.1@9900,6055.78 9910,6065.78 C6_AMP12.2@9910,6108.22
NetC6_AMP13_1: C6_AMP13.1 Q3_AMP13.2 R8_AMP13.1 | length 203.1
  Top Layer w7: 10244.43,6279 10244.43,6262.57 10273.93,6233.07 10292.4,6233.07 10294.78,6230.69 R8_AMP13.1@10294.78,6150 ; C6_AMP13.1@10297,6113.78 10297,6156.22
NetC6_AMP13_2: C6_AMP13.2 R7_AMP13.1 | length 56.6
  Top Layer w7: R7_AMP13.1@10287,6033.78 10297,6043.78 C6_AMP13.2@10297,6086.22
NetC6_AMP14_1: C6_AMP14.1 Q3_AMP14.2 R8_AMP14.1 | length 203.1
  Top Layer w7: 10610.43,6279 10610.43,6262.57 10639.93,6233.07 10658.4,6233.07 10660.78,6230.69 R8_AMP14.1@10660.78,6150 ; C6_AMP14.1@10663,6113.78 10663,6156.22
NetC6_AMP14_2: C6_AMP14.2 R7_AMP14.1 | length 56.6
  Top Layer w7: R7_AMP14.1@10653,6033.78 10663,6043.78 C6_AMP14.2@10663,6086.22
NetC6_AMP15_1: C6_AMP15.1 Q3_AMP15.2 R8_AMP15.1 | length 203.1
  Top Layer w7: 11078.43,6236 11078.43,6219.57 11107.93,6190.07 11126.4,6190.07 11128.78,6187.69 R8_AMP15.1@11128.78,6107 ; C6_AMP15.1@11131,6070.78 11131,6113.22
NetC6_AMP15_2: C6_AMP15.2 R7_AMP15.1 | length 56.6
  Top Layer w7: R7_AMP15.1@11121,5990.78 11131,6000.78 C6_AMP15.2@11131,6043.22
NetC6_AMP16_1: C6_AMP16.1 Q3_AMP16.2 R8_AMP16.1 | length 203.1
  Top Layer w7: 11500.43,6268 11500.43,6251.57 11529.93,6222.07 11548.4,6222.07 11550.78,6219.69 R8_AMP16.1@11550.78,6139 ; C6_AMP16.1@11553,6102.78 11553,6145.22
NetC6_AMP16_2: C6_AMP16.2 R7_AMP16.1 | length 56.6
  Top Layer w7: R7_AMP16.1@11543,6022.78 11553,6032.78 C6_AMP16.2@11553,6075.22
NetC6_AMP17_1: C6_AMP17.1 Q3_AMP17.2 R8_AMP17.1 | length 203.1
  Top Layer w7: 11888.43,6280 11888.43,6263.57 11917.93,6234.07 11936.4,6234.07 11938.78,6231.69 R8_AMP17.1@11938.78,6151 ; C6_AMP17.1@11941,6114.78 11941,6157.22
NetC6_AMP17_2: C6_AMP17.2 R7_AMP17.1 | length 56.6
  Top Layer w7: R7_AMP17.1@11931,6034.78 11941,6044.78 C6_AMP17.2@11941,6087.22
NetC6_AMP18_1: C6_AMP18.1 Q3_AMP18.2 R8_AMP18.1 | length 203.1
  Top Layer w7: 12344.43,6078 12344.43,6061.57 12373.93,6032.07 12392.4,6032.07 12394.78,6029.69 R8_AMP18.1@12394.78,5949 ; C6_AMP18.1@12397,5912.78 12397,5955.22
NetC6_AMP18_2: C6_AMP18.2 R7_AMP18.1 | length 56.6
  Top Layer w7: R7_AMP18.1@12387,5832.78 12397,5842.78 C6_AMP18.2@12397,5885.22
NetC6_AMP19_1: C6_AMP19.1 Q3_AMP19.2 R8_AMP19.1 | length 203.1
  Top Layer w7: 12736.43,6274 12736.43,6257.57 12765.93,6228.07 12784.4,6228.07 12786.78,6225.69 R8_AMP19.1@12786.78,6145 ; C6_AMP19.1@12789,6108.78 12789,6151.22
NetC6_AMP19_2: C6_AMP19.2 R7_AMP19.1 | length 56.6
  Top Layer w7: R7_AMP19.1@12779,6028.78 12789,6038.78 C6_AMP19.2@12789,6081.22
NetC6_AMP20_1: C6_AMP20.1 Q3_AMP20.2 R8_AMP20.1 | length 203.1
  Top Layer w7: 13226.43,6127 13226.43,6110.57 13255.93,6081.07 13274.4,6081.07 13276.78,6078.69 R8_AMP20.1@13276.78,5998 ; C6_AMP20.1@13279,5961.78 13279,6004.22
NetC6_AMP20_2: C6_AMP20.2 R7_AMP20.1 | length 56.6
  Top Layer w7: R7_AMP20.1@13269,5881.78 13279,5891.78 C6_AMP20.2@13279,5934.22
NetC6_AMP21_1: C6_AMP21.1 Q3_AMP21.2 R8_AMP21.1 | length 203.1
  Top Layer w7: 13776.43,6233 13776.43,6216.57 13805.93,6187.07 13824.4,6187.07 13826.78,6184.69 R8_AMP21.1@13826.78,6104 ; C6_AMP21.1@13829,6067.78 13829,6110.22
NetC6_AMP21_2: C6_AMP21.2 R7_AMP21.1 | length 56.6
  Top Layer w7: R7_AMP21.1@13819,5987.78 13829,5997.78 C6_AMP21.2@13829,6040.22
NetC6_AMP22_1: C6_AMP22.1 Q3_AMP22.2 R8_AMP22.1 | length 203.1
  Top Layer w7: 14481.43,6175 14481.43,6158.57 14510.93,6129.07 14529.4,6129.07 14531.78,6126.69 R8_AMP22.1@14531.78,6046 ; C6_AMP22.1@14534,6009.78 14534,6052.22
NetC6_AMP22_2: C6_AMP22.2 R7_AMP22.1 | length 56.6
  Top Layer w7: R7_AMP22.1@14524,5929.78 14534,5939.78 C6_AMP22.2@14534,5982.22
NetC6_AMP23_1: C6_AMP23.1 Q3_AMP23.2 R8_AMP23.1 | length 203.1
  Top Layer w7: 15290.43,6233 15290.43,6216.57 15319.93,6187.07 15338.4,6187.07 15340.78,6184.69 R8_AMP23.1@15340.78,6104 ; C6_AMP23.1@15343,6067.78 15343,6110.22
NetC6_AMP23_2: C6_AMP23.2 R7_AMP23.1 | length 56.6
  Top Layer w7: R7_AMP23.1@15333,5987.78 15343,5997.78 C6_AMP23.2@15343,6040.22
NetC6_AMP24_1: C6_AMP24.1 Q3_AMP24.2 R8_AMP24.1 | length 203.1
  Top Layer w7: 15748.43,6275 15748.43,6258.57 15777.93,6229.07 15796.4,6229.07 15798.78,6226.69 R8_AMP24.1@15798.78,6146 ; C6_AMP24.1@15801,6109.78 15801,6152.22
NetC6_AMP24_2: C6_AMP24.2 R7_AMP24.1 | length 56.6
  Top Layer w7: R7_AMP24.1@15791,6029.78 15801,6039.78 C6_AMP24.2@15801,6082.22
NetC6_AMP25_1: C6_AMP25.1 Q3_AMP25.2 R8_AMP25.1 | length 203.1
  Top Layer w7: 16247.43,6254 16247.43,6237.57 16276.93,6208.07 16295.4,6208.07 16297.78,6205.69 R8_AMP25.1@16297.78,6125 ; C6_AMP25.1@16300,6088.78 16300,6131.22
NetC6_AMP25_2: C6_AMP25.2 R7_AMP25.1 | length 56.6
  Top Layer w7: R7_AMP25.1@16290,6008.78 16300,6018.78 C6_AMP25.2@16300,6061.22
NetC6_AMP26_1: C6_AMP26.1 Q3_AMP26.2 R8_AMP26.1 | length 203.1
  Top Layer w7: 16704.43,6223 16704.43,6206.57 16733.93,6177.07 16752.4,6177.07 16754.78,6174.69 R8_AMP26.1@16754.78,6094 ; C6_AMP26.1@16757,6057.78 16757,6100.22
NetC6_AMP26_2: C6_AMP26.2 R7_AMP26.1 | length 56.6
  Top Layer w7: R7_AMP26.1@16747,5977.78 16757,5987.78 C6_AMP26.2@16757,6030.22
NetC6_AMP27_1: C6_AMP27.1 Q3_AMP27.2 R8_AMP27.1 | length 203.1
  Top Layer w7: 17234.43,6234 17234.43,6217.57 17263.93,6188.07 17282.4,6188.07 17284.78,6185.69 R8_AMP27.1@17284.78,6105 ; C6_AMP27.1@17287,6068.78 17287,6111.22
NetC6_AMP27_2: C6_AMP27.2 R7_AMP27.1 | length 56.6
  Top Layer w7: R7_AMP27.1@17277,5988.78 17287,5998.78 C6_AMP27.2@17287,6041.22
NetC6_AMP28_1: C6_AMP28.1 Q3_AMP28.2 R8_AMP28.1 | length 203.1
  Top Layer w7: 17765.43,6234 17765.43,6217.57 17794.93,6188.07 17813.4,6188.07 17815.78,6185.69 R8_AMP28.1@17815.78,6105 ; C6_AMP28.1@17818,6068.78 17818,6111.22
NetC6_AMP28_2: C6_AMP28.2 R7_AMP28.1 | length 56.6
  Top Layer w7: R7_AMP28.1@17808,5988.78 17818,5998.78 C6_AMP28.2@17818,6041.22
NetC6_AMP29_1: C6_AMP29.1 Q3_AMP29.2 R8_AMP29.1 | length 203.1
  Top Layer w7: 18182.43,6275 18182.43,6258.57 18211.93,6229.07 18230.4,6229.07 18232.78,6226.69 R8_AMP29.1@18232.78,6146 ; C6_AMP29.1@18235,6109.78 18235,6152.22
NetC6_AMP29_2: C6_AMP29.2 R7_AMP29.1 | length 56.6
  Top Layer w7: R7_AMP29.1@18225,6029.78 18235,6039.78 C6_AMP29.2@18235,6082.22
NetC6_AMP30_1: C6_AMP30.1 Q3_AMP30.2 R8_AMP30.1 | length 203.1
  Top Layer w7: 27300.43,6407 27300.43,6390.57 27329.93,6361.07 27348.4,6361.07 27350.78,6358.69 R8_AMP30.1@27350.78,6278 ; C6_AMP30.1@27353,6241.78 27353,6284.22
NetC6_AMP30_2: C6_AMP30.2 R7_AMP30.1 | length 56.6
  Top Layer w7: R7_AMP30.1@27343,6161.78 27353,6171.78 C6_AMP30.2@27353,6214.22
NetC7_SUMMER1_2: C7_SUMMER1.2 Q4_SUMMER1.2 R12_SUMMER1.2 | length 76.4
  Top Layer w7: C7_SUMMER1.2@1560,2453.78 1560,2479.22 1564.78,2484 Q4_SUMMER1.2@1609,2484
NetC7_SUMMER2_2: C7_SUMMER2.2 Q4_SUMMER2.2 R12_SUMMER2.2
NetC7_SUMMER3_2: C7_SUMMER3.2 Q4_SUMMER3.2 R12_SUMMER3.2
NetC7_SUMMER4_2: C7_SUMMER4.2 Q4_SUMMER4.2 R12_SUMMER4.2
NetC7_SUMMER5_2: C7_SUMMER5.2 Q4_SUMMER5.2 R12_SUMMER5.2
NetC7_SUMMER6_2: C7_SUMMER6.2 Q4_SUMMER6.2 R12_SUMMER6.2
NetC8_SUMMER1_1: C8_SUMMER1.1 Q4_SUMMER1.3 Q8_SUMMER1.1 R11_SUMMER1.1 | length 315.6
  Top Layer w7: Q4_SUMMER1.3@1712,2522 1712,2505 1725.78,2491.22 R11_SUMMER1.1@1760,2491.22 ; R11_SUMMER1.1@1760,2492.6 1963.6,2492.6 1970,2499 C8_SUMMER1.1@1970,2531.22
NetC8_SUMMER1_2: C8_SUMMER1.2 M1_SUMMER1.3 | length 154.6
  Top Layer w7: M1_SUMMER1.3@1892.6,2666.69 1892.6,2639.4 1919,2613 1944,2613 1970,2587 C8_SUMMER1.2@1970,2558.78
NetC8_SUMMER2_1: C8_SUMMER2.1 Q4_SUMMER2.3 Q8_SUMMER2.1 R11_SUMMER2.1
NetC8_SUMMER2_2: C8_SUMMER2.2 M1_SUMMER2.3
NetC8_SUMMER3_1: C8_SUMMER3.1 Q4_SUMMER3.3 Q8_SUMMER3.1 R11_SUMMER3.1
NetC8_SUMMER3_2: C8_SUMMER3.2 M1_SUMMER3.3
NetC8_SUMMER4_1: C8_SUMMER4.1 Q4_SUMMER4.3 Q8_SUMMER4.1 R11_SUMMER4.1
NetC8_SUMMER4_2: C8_SUMMER4.2 M1_SUMMER4.3
NetC8_SUMMER5_1: C8_SUMMER5.1 Q4_SUMMER5.3 Q8_SUMMER5.1 R11_SUMMER5.1
NetC8_SUMMER5_2: C8_SUMMER5.2 M1_SUMMER5.3
NetC8_SUMMER6_1: C8_SUMMER6.1 Q4_SUMMER6.3 Q8_SUMMER6.1 R11_SUMMER6.1
NetC8_SUMMER6_2: C8_SUMMER6.2 M1_SUMMER6.3
NetC9_SUMMER1_1: C9_SUMMER1.1 Q7_SUMMER1.2 R16_SUMMER1.1 | length 99.1
  Top Layer w7: C9_SUMMER1.1@1285,2533.78 R16_SUMMER1.1@1285,2572.6 ; R16_SUMMER1.1@1285,2571.22 1297.06,2571.22 1310.84,2585 1339.57,2585
NetC9_SUMMER2_1: C9_SUMMER2.1 Q7_SUMMER2.2 R16_SUMMER2.1
NetC9_SUMMER3_1: C9_SUMMER3.1 Q7_SUMMER3.2 R16_SUMMER3.1
NetC9_SUMMER4_1: C9_SUMMER4.1 Q7_SUMMER4.2 R16_SUMMER4.1
NetC9_SUMMER5_1: C9_SUMMER5.1 Q7_SUMMER5.2 R16_SUMMER5.1
NetC9_SUMMER6_1: C9_SUMMER6.1 Q7_SUMMER6.2 R16_SUMMER6.1
NetCBi_AMP1_1: CBi_AMP1.1 Q0_AMP1.1 RBi_AMP1.2 | length 90.9
  Top Layer w7: CBi_AMP1.1@1259,1596.22 RBi_AMP1.2@1299,1596.22 ; Q0_AMP1.1@1288,1544.3 1288,1595.22
NetCBi_AMP2_1: CBi_AMP2.1 Q0_AMP2.1 RBi_AMP2.2 | length 90.9
  Top Layer w7: CBi_AMP2.1@1442,1596.22 RBi_AMP2.2@1482,1596.22 ; Q0_AMP2.1@1471,1544.3 1471,1595.22
NetCBi_AMP3_1: CBi_AMP3.1 Q0_AMP3.1 RBi_AMP3.2 | length 90.9
  Top Layer w7: CBi_AMP3.1@1625,1596.22 RBi_AMP3.2@1665,1596.22 ; Q0_AMP3.1@1654,1544.3 1654,1595.22
NetCBi_AMP4_1: CBi_AMP4.1 Q0_AMP4.1 RBi_AMP4.2 | length 90.9
  Top Layer w7: CBi_AMP4.1@1809,1596.22 RBi_AMP4.2@1849,1596.22 ; Q0_AMP4.1@1838,1544.3 1838,1595.22
NetCBi_AMP5_1: CBi_AMP5.1 Q0_AMP5.1 RBi_AMP5.2 | length 90.9
  Top Layer w7: CBi_AMP5.1@1992,1596.22 RBi_AMP5.2@2032,1596.22 ; Q0_AMP5.1@2021,1544.3 2021,1595.22
NetCBi_AMP6_1: CBi_AMP6.1 Q0_AMP6.1 RBi_AMP6.2 | length 90.9
  Top Layer w7: CBi_AMP6.1@6955,5856.22 RBi_AMP6.2@6995,5856.22 ; Q0_AMP6.1@6984,5804.3 6984,5855.22
NetCBi_AMP7_1: CBi_AMP7.1 Q0_AMP7.1 RBi_AMP7.2 | length 90.9
  Top Layer w7: CBi_AMP7.1@7417,5851.22 RBi_AMP7.2@7457,5851.22 ; Q0_AMP7.1@7446,5799.3 7446,5850.22
NetCBi_AMP8_1: CBi_AMP8.1 Q0_AMP8.1 RBi_AMP8.2 | length 90.9
  Top Layer w7: CBi_AMP8.1@7914,5875.22 RBi_AMP8.2@7954,5875.22 ; Q0_AMP8.1@7943,5823.3 7943,5874.22
NetCBi_AMP9_1: CBi_AMP9.1 Q0_AMP9.1 RBi_AMP9.2 | length 90.9
  Top Layer w7: CBi_AMP9.1@8365,5868.22 RBi_AMP9.2@8405,5868.22 ; Q0_AMP9.1@8394,5816.3 8394,5867.22
NetCBi_AMP10_1: CBi_AMP10.1 Q0_AMP10.1 RBi_AMP10.2 | length 90.9
  Top Layer w7: CBi_AMP10.1@8794,5851.22 RBi_AMP10.2@8834,5851.22 ; Q0_AMP10.1@8823,5799.3 8823,5850.22
NetCBi_AMP11_1: CBi_AMP11.1 Q0_AMP11.1 RBi_AMP11.2 | length 90.9
  Top Layer w7: CBi_AMP11.1@9206,5827.22 RBi_AMP11.2@9246,5827.22 ; Q0_AMP11.1@9235,5775.3 9235,5826.22
NetCBi_AMP12_1: CBi_AMP12.1 Q0_AMP12.1 RBi_AMP12.2 | length 90.9
  Top Layer w7: CBi_AMP12.1@9770,5849.22 RBi_AMP12.2@9810,5849.22 ; Q0_AMP12.1@9799,5797.3 9799,5848.22
NetCBi_AMP13_1: CBi_AMP13.1 Q0_AMP13.1 RBi_AMP13.2 | length 90.9
  Top Layer w7: CBi_AMP13.1@10157,5827.22 RBi_AMP13.2@10197,5827.22 ; Q0_AMP13.1@10186,5775.3 10186,5826.22
NetCBi_AMP14_1: CBi_AMP14.1 Q0_AMP14.1 RBi_AMP14.2 | length 90.9
  Top Layer w7: CBi_AMP14.1@10523,5827.22 RBi_AMP14.2@10563,5827.22 ; Q0_AMP14.1@10552,5775.3 10552,5826.22
NetCBi_AMP15_1: CBi_AMP15.1 Q0_AMP15.1 RBi_AMP15.2 | length 90.9
  Top Layer w7: CBi_AMP15.1@10991,5784.22 RBi_AMP15.2@11031,5784.22 ; Q0_AMP15.1@11020,5732.3 11020,5783.22
NetCBi_AMP16_1: CBi_AMP16.1 Q0_AMP16.1 RBi_AMP16.2 | length 90.9
  Top Layer w7: CBi_AMP16.1@11413,5816.22 RBi_AMP16.2@11453,5816.22 ; Q0_AMP16.1@11442,5764.3 11442,5815.22
NetCBi_AMP17_1: CBi_AMP17.1 Q0_AMP17.1 RBi_AMP17.2 | length 90.9
  Top Layer w7: CBi_AMP17.1@11801,5828.22 RBi_AMP17.2@11841,5828.22 ; Q0_AMP17.1@11830,5776.3 11830,5827.22
NetCBi_AMP18_1: CBi_AMP18.1 Q0_AMP18.1 RBi_AMP18.2 | length 90.9
  Top Layer w7: CBi_AMP18.1@12257,5626.22 RBi_AMP18.2@12297,5626.22 ; Q0_AMP18.1@12286,5574.3 12286,5625.22
NetCBi_AMP19_1: CBi_AMP19.1 Q0_AMP19.1 RBi_AMP19.2 | length 90.9
  Top Layer w7: CBi_AMP19.1@12649,5822.22 RBi_AMP19.2@12689,5822.22 ; Q0_AMP19.1@12678,5770.3 12678,5821.22
NetCBi_AMP20_1: CBi_AMP20.1 Q0_AMP20.1 RBi_AMP20.2 | length 90.9
  Top Layer w7: CBi_AMP20.1@13139,5675.22 RBi_AMP20.2@13179,5675.22 ; Q0_AMP20.1@13168,5623.3 13168,5674.22
NetCBi_AMP21_1: CBi_AMP21.1 Q0_AMP21.1 RBi_AMP21.2 | length 90.9
  Top Layer w7: CBi_AMP21.1@13689,5781.22 RBi_AMP21.2@13729,5781.22 ; Q0_AMP21.1@13718,5729.3 13718,5780.22
NetCBi_AMP22_1: CBi_AMP22.1 Q0_AMP22.1 RBi_AMP22.2 | length 90.9
  Top Layer w7: CBi_AMP22.1@14394,5723.22 RBi_AMP22.2@14434,5723.22 ; Q0_AMP22.1@14423,5671.3 14423,5722.22
NetCBi_AMP23_1: CBi_AMP23.1 Q0_AMP23.1 RBi_AMP23.2 | length 90.9
  Top Layer w7: CBi_AMP23.1@15203,5781.22 RBi_AMP23.2@15243,5781.22 ; Q0_AMP23.1@15232,5729.3 15232,5780.22
NetCBi_AMP24_1: CBi_AMP24.1 Q0_AMP24.1 RBi_AMP24.2 | length 90.9
  Top Layer w7: CBi_AMP24.1@15661,5823.22 RBi_AMP24.2@15701,5823.22 ; Q0_AMP24.1@15690,5771.3 15690,5822.22
NetCBi_AMP25_1: CBi_AMP25.1 Q0_AMP25.1 RBi_AMP25.2 | length 90.9
  Top Layer w7: CBi_AMP25.1@16160,5802.22 RBi_AMP25.2@16200,5802.22 ; Q0_AMP25.1@16189,5750.3 16189,5801.22
NetCBi_AMP26_1: CBi_AMP26.1 Q0_AMP26.1 RBi_AMP26.2 | length 90.9
  Top Layer w7: CBi_AMP26.1@16617,5771.22 RBi_AMP26.2@16657,5771.22 ; Q0_AMP26.1@16646,5719.3 16646,5770.22
NetCBi_AMP27_1: CBi_AMP27.1 Q0_AMP27.1 RBi_AMP27.2 | length 90.9
  Top Layer w7: CBi_AMP27.1@17147,5782.22 RBi_AMP27.2@17187,5782.22 ; Q0_AMP27.1@17176,5730.3 17176,5781.22
NetCBi_AMP28_1: CBi_AMP28.1 Q0_AMP28.1 RBi_AMP28.2 | length 90.9
  Top Layer w7: CBi_AMP28.1@17678,5782.22 RBi_AMP28.2@17718,5782.22 ; Q0_AMP28.1@17707,5730.3 17707,5781.22
NetCBi_AMP29_1: CBi_AMP29.1 Q0_AMP29.1 RBi_AMP29.2 | length 90.9
  Top Layer w7: CBi_AMP29.1@18095,5823.22 RBi_AMP29.2@18135,5823.22 ; Q0_AMP29.1@18124,5771.3 18124,5822.22
NetCBi_AMP30_1: CBi_AMP30.1 Q0_AMP30.1 RBi_AMP30.2 | length 90.9
  Top Layer w7: CBi_AMP30.1@27213,5955.22 RBi_AMP30.2@27253,5955.22 ; Q0_AMP30.1@27242,5903.3 27242,5954.22
NetCBi_SUMMER1_1: CBi_SUMMER1.1 Q4_SUMMER1.1 RBi_SUMMER1.2 | length 79.2
  Top Layer w7: RBi_SUMMER1.2@1562.4,2520 CBi_SUMMER1.1@1562.4,2555 ; CBi_SUMMER1.1@1564.78,2556 Q4_SUMMER1.1@1609,2556
NetCBi_SUMMER2_1: CBi_SUMMER2.1 Q4_SUMMER2.1 RBi_SUMMER2.2
NetCBi_SUMMER3_1: CBi_SUMMER3.1 Q4_SUMMER3.1 RBi_SUMMER3.2
NetCBi_SUMMER4_1: CBi_SUMMER4.1 Q4_SUMMER4.1 RBi_SUMMER4.2
NetCBi_SUMMER5_1: CBi_SUMMER5.1 Q4_SUMMER5.1 RBi_SUMMER5.2
NetCBi_SUMMER6_1: CBi_SUMMER6.1 Q4_SUMMER6.1 RBi_SUMMER6.2
NetCG_SUMMER1_1: CG_SUMMER1.1 M1_SUMMER1.1 RG_SUMMER1.1 | length 112.6
  Top Layer w7: M1_SUMMER1.1@1959.53,2753.31 2037.09,2753.31 2041.22,2749.17 CG_SUMMER1.1@2041.22,2720
NetCG_SUMMER2_1: CG_SUMMER2.1 M1_SUMMER2.1 RG_SUMMER2.1
NetCG_SUMMER3_1: CG_SUMMER3.1 M1_SUMMER3.1 RG_SUMMER3.1
NetCG_SUMMER4_1: CG_SUMMER4.1 M1_SUMMER4.1 RG_SUMMER4.1
NetCG_SUMMER5_1: CG_SUMMER5.1 M1_SUMMER5.1 RG_SUMMER5.1
NetCG_SUMMER6_1: CG_SUMMER6.1 M1_SUMMER6.1 RG_SUMMER6.1
NetM1_SUMMER1_4: M1_SUMMER1.4 R10_SUMMER1.1 | length 79.2
  Top Layer w7: M1_SUMMER1.4@1967.4,2666.69 1995.31,2638.78 R10_SUMMER1.1@2035,2638.78
NetM1_SUMMER2_4: M1_SUMMER2.4 R10_SUMMER2.1
NetM1_SUMMER3_4: M1_SUMMER3.4 R10_SUMMER3.1
NetM1_SUMMER4_4: M1_SUMMER4.4 R10_SUMMER4.1
NetM1_SUMMER5_4: M1_SUMMER5.4 R10_SUMMER5.1
NetM1_SUMMER6_4: M1_SUMMER6.4 R10_SUMMER6.1
NetQ1_AMP1_3: Q1_AMP1.3 Q2_AMP1.1 Q3_AMP1.1 R2_AMP1.2 R4_AMP1.1 | length 819.5
  Top Layer w7: Q1_AMP1.3@1282.66,2229 1405,2229 1405,2111 1384,2090 1333,2090 1313,2070 1313,2056 1279.41,2022.41 1275.57,2022.41 1259,2005.84 1259,1941.2 1270.1,1930.1 1270,1930.1 1270,1876 1273,1873 1301,1873 1326.59,1847.41 1326.59,1816.59 1315.22,1805.22 1315.22,1717.78 1340.22,1692.78 R2_AMP1.2@1349,1692.78
NetQ1_AMP2_3: Q1_AMP2.3 Q2_AMP2.1 Q3_AMP2.1 R2_AMP2.2 R4_AMP2.1 | length 819.5
  Top Layer w7: Q1_AMP2.3@1465.66,2229 1588,2229 1588,2111 1567,2090 1516,2090 1496,2070 1496,2056 1462.41,2022.41 1458.57,2022.41 1442,2005.84 1442,1941.2 1453.1,1930.1 1453,1930.1 1453,1876 1456,1873 1484,1873 1509.59,1847.41 1509.59,1816.59 1498.22,1805.22 1498.22,1717.78 1523.22,1692.78 R2_AMP2.2@1532,1692.78
NetQ1_AMP3_3: Q1_AMP3.3 Q2_AMP3.1 Q3_AMP3.1 R2_AMP3.2 R4_AMP3.1 | length 819.5
  Top Layer w7: Q1_AMP3.3@1648.66,2229 1771,2229 1771,2111 1750,2090 1699,2090 1679,2070 1679,2056 1645.41,2022.41 1641.57,2022.41 1625,2005.84 1625,1941.2 1636.1,1930.1 1636,1930.1 1636,1876 1639,1873 1667,1873 1692.59,1847.41 1692.59,1816.59 1681.22,1805.22 1681.22,1717.78 1706.22,1692.78 R2_AMP3.2@1715,1692.78
NetQ1_AMP4_3: Q1_AMP4.3 Q2_AMP4.1 Q3_AMP4.1 R2_AMP4.2 R4_AMP4.1 | length 819.5
  Top Layer w7: Q1_AMP4.3@1832.66,2229 1955,2229 1955,2111 1934,2090 1883,2090 1863,2070 1863,2056 1829.41,2022.41 1825.57,2022.41 1809,2005.84 1809,1941.2 1820.1,1930.1 1820,1930.1 1820,1876 1823,1873 1851,1873 1876.59,1847.41 1876.59,1816.59 1865.22,1805.22 1865.22,1717.78 1890.22,1692.78 R2_AMP4.2@1899,1692.78
NetQ1_AMP5_3: Q1_AMP5.3 Q2_AMP5.1 Q3_AMP5.1 R2_AMP5.2 R4_AMP5.1 | length 819.5
  Top Layer w7: Q1_AMP5.3@2015.66,2229 2138,2229 2138,2111 2117,2090 2066,2090 2046,2070 2046,2056 2012.41,2022.41 2008.57,2022.41 1992,2005.84 1992,1941.2 2003.1,1930.1 2003,1930.1 2003,1876 2006,1873 2034,1873 2059.59,1847.41 2059.59,1816.59 2048.22,1805.22 2048.22,1717.78 2073.22,1692.78 R2_AMP5.2@2082,1692.78
NetQ1_AMP6_3: Q1_AMP6.3 Q2_AMP6.1 Q3_AMP6.1 R2_AMP6.2 R4_AMP6.1 | length 369.6
  Top Layer w7: Q2_AMP6.1@6962,6107.44 6985.34,6130.78 7003.47,6130.78 7015.59,6142.91 7015.59,6196.41 6984.41,6227.59 Q3_AMP6.1@6984.41,6244.57 ; Q2_AMP6.1@6962.41,6099.57 6962.41,6086.59 7012.6,6036.4 7012.6,6024.62 7026.22,6011 R4_AMP6.1@7026.22,5988 R4_AMP6.1@7029.49,5984.73 ; R4_AMP6.1@7027.6,5988 7027.6,5977.24 7042.4,5962.44 R2_AMP6.2@7042.4,5950
NetQ1_AMP7_3: Q1_AMP7.3 Q2_AMP7.1 Q3_AMP7.1 R2_AMP7.2 R4_AMP7.1 | length 902.3
  Top Layer w7: Q3_AMP7.1@7433.57,6328.59 7433.57,6357.57 v1(7461,6385) v1@7471.57,6374.43 ; Q1_AMP7.3@7440.66,6484 7563,6484 7563,6366 7542,6345 7491,6345 7471,6325 7471,6311 7437.41,6277.41 7433.57,6277.41 7417,6260.84 7417,6196.2 7428.1,6185.1 7428,6185.1 7428,6131 7431,6128 7459,6128 7484.59,6102.41 7484.59,6071.59 7473.22,6060.22 7473.22,5972.78 7498.22,5947.78 R2_AMP7.2@7507,5947.78
NetQ1_AMP8_3: Q1_AMP8.3 Q2_AMP8.1 Q3_AMP8.1 R2_AMP8.2 R4_AMP8.1 | length 902.3
  Top Layer w7: Q3_AMP8.1@7930.57,6352.59 7930.57,6381.57 v1(7958,6409) v1@7968.57,6398.43 ; Q1_AMP8.3@7937.66,6508 8060,6508 8060,6390 8039,6369 7988,6369 7968,6349 7968,6335 7934.41,6301.41 7930.57,6301.41 7914,6284.84 7914,6220.2 7925.1,6209.1 7925,6209.1 7925,6155 7928,6152 7956,6152 7981.59,6126.41 7981.59,6095.59 7970.22,6084.22 7970.22,5996.78 7995.22,5971.78 R2_AMP8.2@8004,5971.78
NetQ1_AMP9_3: Q1_AMP9.3 Q2_AMP9.1 Q3_AMP9.1 R2_AMP9.2 R4_AMP9.1 | length 902.3
  Top Layer w7: Q3_AMP9.1@8381.57,6345.59 8381.57,6374.57 v1(8409,6402) v1@8419.57,6391.43 ; Q1_AMP9.3@8388.66,6501 8511,6501 8511,6383 8490,6362 8439,6362 8419,6342 8419,6328 8385.41,6294.41 8381.57,6294.41 8365,6277.84 8365,6213.2 8376.1,6202.1 8376,6202.1 8376,6148 8379,6145 8407,6145 8432.59,6119.41 8432.59,6088.59 8421.22,6077.22 8421.22,5989.78 8446.22,5964.78 R2_AMP9.2@8455,5964.78
NetQ1_AMP10_3: Q1_AMP10.3 Q2_AMP10.1 Q3_AMP10.1 R2_AMP10.2 R4_AMP10.1 | length 902.3
  Top Layer w7: Q3_AMP10.1@8810.57,6328.59 8810.57,6357.57 v1(8838,6385) v1@8848.57,6374.43 ; Q1_AMP10.3@8817.66,6484 8940,6484 8940,6366 8919,6345 8868,6345 8848,6325 8848,6311 8814.41,6277.41 8810.57,6277.41 8794,6260.84 8794,6196.2 8805.1,6185.1 8805,6185.1 8805,6131 8808,6128 8836,6128 8861.59,6102.41 8861.59,6071.59 8850.22,6060.22 8850.22,5972.78 8875.22,5947.78 R2_AMP10.2@8884,5947.78
NetQ1_AMP11_3: Q1_AMP11.3 Q2_AMP11.1 Q3_AMP11.1 R2_AMP11.2 R4_AMP11.1 | length 902.3
  Top Layer w7: Q3_AMP11.1@9222.57,6304.59 9222.57,6333.57 v1(9250,6361) v1@9260.57,6350.43 ; Q1_AMP11.3@9229.66,6460 9352,6460 9352,6342 9331,6321 9280,6321 9260,6301 9260,6287 9226.41,6253.41 9222.57,6253.41 9206,6236.84 9206,6172.2 9217.1,6161.1 9217,6161.1 9217,6107 9220,6104 9248,6104 9273.59,6078.41 9273.59,6047.59 9262.22,6036.22 9262.22,5948.78 9287.22,5923.78 R2_AMP11.2@9296,5923.78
